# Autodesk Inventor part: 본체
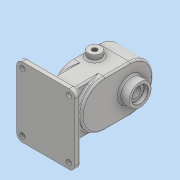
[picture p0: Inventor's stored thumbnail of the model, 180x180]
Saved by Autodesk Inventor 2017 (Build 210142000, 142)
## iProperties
Part Number: 본체
Material: 일반
Document SubType Name: Modeling
Designer: 222
Density: 1 g/cm^3
Appearance: 기본값
Author: 222
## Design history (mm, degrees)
sketch "스케치1"
  geometry: L1 (22, 0)-(-22, 0); L2 (22, -40)-(-22, -40); L3 (-22, 40)-(22, 40); A1 r 40 centre (22, 0) between (22, -40) and (22, 40); A2 r 40 centre (-22, 0) between (-22, 40) and (-22, -40); 2 further points
  constraints: 8 end point, 4 point on circle, 4 tangent, 2 centre point, 1 coincident, 1 horizontal, 1 midpoint, 1 parallel
  dimensions: "d0" = 40 radius of A1; "d1" = 44 distance of L3.start L3.end
extrude "돌출1" new body sketch "스케치1" stored distance "d2" = 53; taper "d3" = 0 deg
sketch "스케치2"
  geometry: L1 (0, -22)-(0, 22); L2 (-24, -22)-(-24, 22); L3 (24, 22)-(24, -22); A1 r 24 centre (0, -22) between (-24, -22) and (24, -22); A2 r 24 centre (0, 22) between (24, 22) and (-24, 22); 2 further points
  constraints: 8 end point, 4 point on circle, 4 tangent, 2 centre point, 1 coincident, 1 midpoint, 1 parallel, 1 vertical
  dimensions: "d4" = 24 radius of A2; "d5" = 44 distance of L3.start L3.end
extrude "돌출2" cut sketch "스케치2" distance "d6" = 29; taper "d7" = 0 deg
sketch "스케치3"
  geometry: C1 r 19 at (0, 22); A1 r 40 centre (0, 22) between (40, 22) and (-40, 22) reference; 1 further point
  constraints: 1 centre point, 1 coincident
  dimensions: "d8" = 38 diameter of C1
extrude "돌출3" join sketch "스케치3" distance "d9" = 17; taper "d10" = 0 deg
hole "구멍1" diameter "d13" = 28; stored, may be unused: countersink angle "d17" = 90 deg, drill point angle "d19" = 0 deg; dims "d14" = 6, "d15" = 4, "d16" = 2, "d18" = 7.3, "d100" = 10, "d101" = 10
hole "구멍2" diameter "d22" = 25; stored, may be unused: countersink angle "d26" = 90 deg, drill point angle "d28" = 0 deg; dims "d20" = 10, "d21" = 10, "d23" = 6, "d24" = 4, "d25" = 2, "d27" = 15
hole "구멍3" diameter "d31" = 17; stored, may be unused: countersink angle "d35" = 90 deg, drill point angle "d37" = 0 deg; dims "d29" = 10, "d30" = 10, "d32" = 6, "d33" = 4, "d34" = 2, "d36" = 15
hole "구멍4" diameter "d40" = 25; stored, may be unused: countersink angle "d44" = 90 deg, drill point angle "d46" = 0 deg; dims "d38" = 10, "d39" = 10, "d41" = 6, "d42" = 4, "d43" = 2, "d45" = 15
sketch "스케치5"
  geometry: L1 (0, 0)-(0, 44) reference; C1 r 11 at (14, 22); 1 further point
  constraints: 1 centre point, 1 horizontal alignment
  dimensions: "d47" = 22 diameter of C1; "d48" = 14 distance from line of C1.centre L1
extrude "돌출4" join sketch "스케치5" distance "d49" = 10; taper "d50" = 0 deg
hole "구멍5" diameter "d53" = 8.376; stored, may be unused: countersink angle "d57" = 90 deg, drill point angle "d59" = 0 deg; dims "d51" = 10, "d52" = 10, "d54" = 20, "d55" = 4, "d56" = 2, "d58" = 27.3
sketch "스케치6"
  geometry: L1 (40, -22)-(40, 22) reference; L2 (-40, 22)-(-40, -22) reference; L3 (31, 22)-(31, -22); L4 (-31, -22)-(-31, 22); A1 r 40 centre (0, 22) between (40, 22) and (-40, 22) reference; A2 r 40 centre (0, -22) between (-40, -22) and (40, -22) reference; A3 r 31 centre (0, 22) between (31, 22) and (-31, 22); A4 r 31 centre (0, -22) between (-31, -22) and (31, -22); 7 further points
  constraints: 6 point on circle, 4 coincident, 4 end point, 2 centre point, 3 other
  dimensions: "d60" = 31 radius of A3
hole "구멍6" sketch "스케치6" at (0, 53), (-31, 22), (31, 22), (31, -22), (-31, -22), (0, -53) diameter "d61" = 4.134; stored, may be unused: countersink angle "d65" = 90 deg, drill point angle "d67" = 0 deg; dims "d62" = 10, "d63" = 4, "d64" = 2, "d66" = 12
node "작업 평면1"
sketch "스케치7"
  geometry: L1 (56.5, -60)-(-43.5, -60); L2 (-43.5, -60)-(-43.5, 60); L3 (-43.5, 60)-(56.5, 60); L4 (56.5, 60)-(56.5, -60); L5 (-43.5, 19)-(-43.5, -19) reference; 2 further points
  constraints: 8 end point, 2 midpoint, 2 parallel, 1 horizontal, 1 perpendicular
  dimensions: "d69" = 100 distance of L1.start L1.end; "d70" = 120 distance of L3.end L1.start
extrude "돌출5" join sketch "스케치7" distance "d71" = 10; taper "d72" = 0 deg
sketch "스케치8"
  geometry: L1 (18.5, 40)-(-18.5, 40); L2 (-18.5, 40)-(-18.5, -40); L3 (-18.5, -40)-(18.5, -40); L4 (18.5, -40)-(18.5, 40); L5 (43.5, 60)-(43.5, -60) reference; L6 (-26.5, 40)-(26.5, 40) reference; L7 (26.5, -40)-(-26.5, -40) reference; 1 further point
  constraints: 8 end point, 2 parallel, 1 collinear, 1 horizontal, 1 perpendicular
  dimensions: "d73" = 80 distance of L3.end L1.start; "d74" = 37 distance of L2.end L3.end; "d75" = 25 distance between parallel lines of L4 L5
extrude "돌출6" join sketch "스케치8" stored distance "d76" = 10; taper "d77" = 0 deg
sketch "스케치9"
  geometry: L1 (43.5, 60)-(-56.5, 60) reference; L2 (-56.5, 60)-(-56.5, -60) reference; 2 further points
  constraints: 1 other
  dimensions: "d78" = 60 distance from line of point (-44.5, 0) L1; "d79" = 12 distance from line of point (-44.5, 0) L2
feature "엠보싱1" sketch "스케치9" dims "d0" = 40, "d1" = 44, "d80" = 0.5, "d81" = 0
fillet "모깎기1" dims "d82" = 10
sketch "스케치10"
  geometry: A1 r 10 centre (-46.5, -50) between (-56.5, -50) and (-46.5, -60) reference; A2 r 10 centre (-46.5, 50) between (-46.5, 60) and (-56.5, 50) reference; A3 r 10 centre (33.5, 50) between (43.5, 50) and (33.5, 60) reference; A4 r 10 centre (33.5, -50) between (33.5, -60) and (43.5, -50) reference; 5 further points
  constraints: 4 coincident
hole "구멍7" sketch "스케치10" at (-46.5, -50), (33.5, -50), (33.5, 50), (-46.5, 50) diameter "d83" = 9; stored, may be unused: countersink angle "d87" = 90 deg, drill point angle "d89" = 0 deg; dims "d84" = 10, "d85" = 4, "d86" = 2, "d88" = 12
fillet "모깎기2" dims "d90" = 3
fillet "모깎기3" dims "d91" = 3
fillet "모깎기4" dims "d92" = 3
fillet "모깎기5" dims "d93" = 0.5
chamfer "모따기1" distance "d94" = 0.7; stored, may be unused: second distance "d95" = 2, angle "d96" = 30 deg
chamfer "모따기2" distance "d97" = 1; stored, may be unused: second distance "d98" = 2, angle "d99" = 30 deg
fillet "모깎기6" dims "d102" = 3
node "솔리드1"
mirror "미러1"
